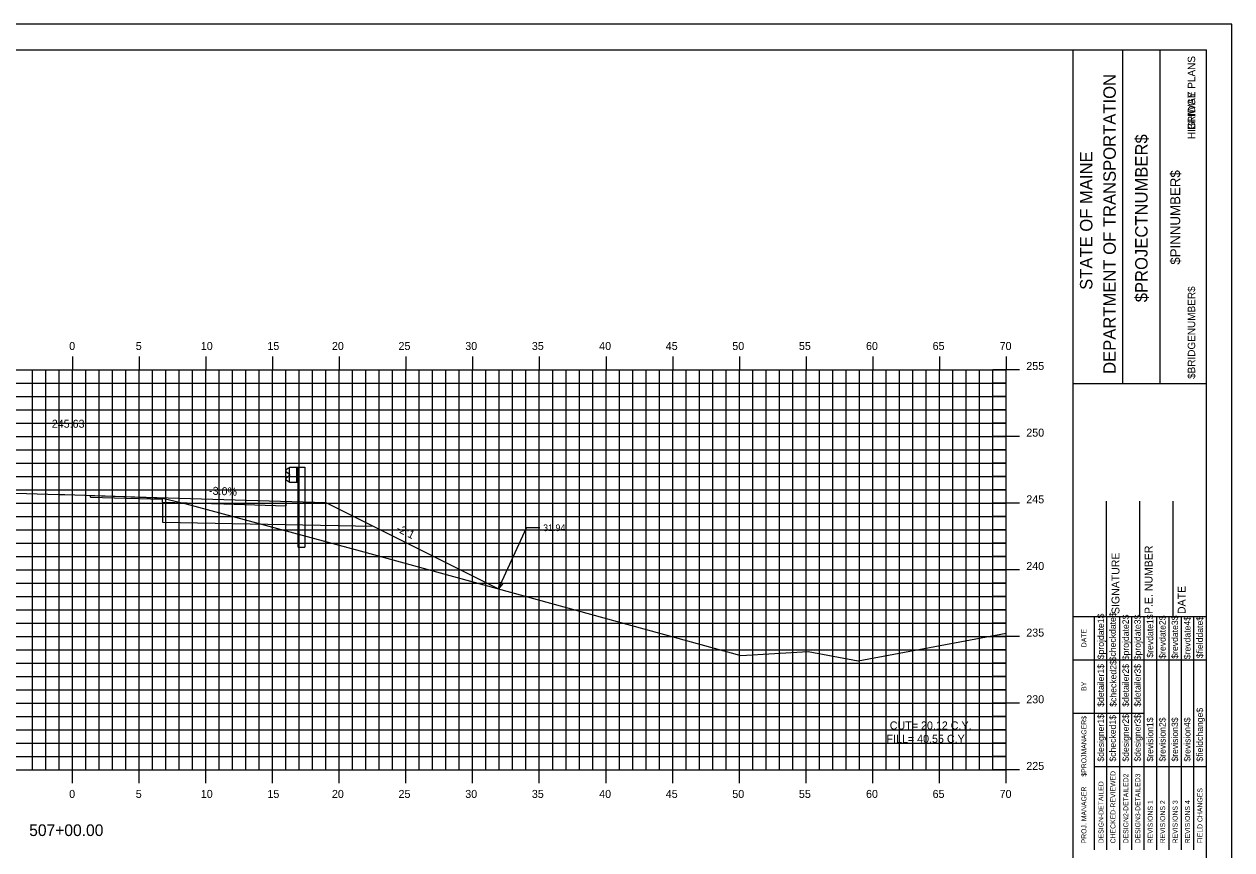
# Model space of a CAD drawing. Extents: x 1170543 to 1177585, y 609599 to 610623.
# Drawn here: x 1171583.6 to 1171674.1, y 609646.9 to 609708.8 of the extents above; entities that cross this region are included whole.
import ezdxf

# ---------------------------------------------------------------- set-up
doc = ezdxf.new("R2010")
doc.units = 0
for name, color, linetype in [('ANNOTATION', 7, 'Continuous'), ('BORDER', 7, 'Continuous'), ('BRIDGE_TITLE', 7, 'Continuous'), ('D_Guardrail_Beam_Rt', 7, 'Continuous'), ('D_Roadway_Centerline', 7, 'Continuous'), ('D_Roadway_Centerline_Text', 7, 'Continuous'), ('H_V ANNOTATION', 7, 'Continuous'), ('HIGHWAY_TITLE', 7, 'Continuous'), ('MAJOR', 7, 'Continuous'), ('MINOR', 7, 'Continuous'), ('PLOT BOUNDARY', 7, 'Continuous'), ('S_Roadway_Centerline', 7, 'Continuous'), ('SHADING', 7, 'Continuous')]:
    doc.layers.add(name, color=color, linetype=linetype)

msp = doc.modelspace()

# ---------------------------------------------------------------- linework, layer by layer
at = {"layer": 'ANNOTATION'}
for p, q in [((1171588.564, 609673.337), (1171588.564, 609673.462)), ((1171593.964, 609672.966), (1171593.964, 609673.3)), ((1171593.964, 609672.966), (1171593.964, 609671.466)), ((1171603.205, 609673.022), (1171603.205, 609672.689)), ((1171619.15, 609666.458), (1171621.24, 609671.034)), ((1171622.24, 609671.034), (1171621.24, 609671.034))]:
    msp.add_line(p, q, dxfattribs=at)
for points in [[(1171588.564, 609673.462), (1171598.564, 609673.162), (1171606.2, 609672.933)], [(1171588.564, 609673.337), (1171593.964, 609673.175)], [(1171593.964, 609672.966), (1171598.564, 609672.828), (1171603.205, 609672.689)], [(1171606.2, 609672.933), (1171608.2, 609671.933), (1171619.15, 609666.458)]]:
    msp.add_lwpolyline(points, dxfattribs=at)
msp.add_lwpolyline([(1171619.471, 609666.861), (1171619.15, 609666.458), (1171619.244, 609666.964)], close=True, dxfattribs=at)
at = {"layer": 'BORDER'}
for p, q in [((1171672.209, 609706.872), (1171512.209, 609706.872)), ((1171662.209, 609601.875), (1171662.209, 609706.875)), ((1171665.937, 609681.869), (1171665.937, 609706.869)), ((1171668.732, 609681.869), (1171668.732, 609706.869)), ((1171672.209, 609601.875), (1171672.209, 609706.875)), ((1171662.209, 609681.866), (1171672.209, 609681.866)), ((1171664.709, 609664.375), (1171664.709, 609673.023)), ((1171667.209, 609664.375), (1171667.209, 609673.023)), ((1171669.709, 609664.375), (1171669.709, 609673.023)), ((1171662.209, 609664.375), (1171672.209, 609664.375))]:
    msp.add_line(p, q, dxfattribs=at)
for points in [[(1171663.823, 609661.125), (1171663.823, 609664.375)], [(1171664.756, 609646.878), (1171664.756, 609664.375)], [(1171665.688, 609664.375), (1171665.688, 609646.878)], [(1171666.619, 609646.878), (1171666.619, 609664.375)], [(1171667.551, 609646.878), (1171667.551, 609664.375)], [(1171668.483, 609646.878), (1171668.483, 609664.375)], [(1171669.414, 609646.878), (1171669.414, 609664.375)], [(1171670.346, 609646.878), (1171670.346, 609664.375)], [(1171671.278, 609646.878), (1171671.278, 609664.375)], [(1171663.824, 609646.878), (1171663.824, 609663.669)], [(1171662.209, 609661.125), (1171672.209, 609661.125)], [(1171662.209, 609657.125), (1171663.824, 609657.125)], [(1171663.823, 609657.125), (1171667.55, 609657.125)], [(1171663.823, 609653.125), (1171672.209, 609653.125)]]:
    msp.add_lwpolyline(points, dxfattribs=at)
at = {"layer": 'D_Guardrail_Beam_Rt'}
for p, q in [((1171603.386, 609675.483), (1171603.243, 609675.383)), ((1171603.243, 609675.239), (1171603.438, 609675.103)), ((1171603.438, 609674.904), (1171603.243, 609674.768)), ((1171603.476, 609675.504), (1171603.402, 609675.489)), ((1171603.472, 609675.039), (1171603.472, 609674.969)), ((1171603.476, 609675.587), (1171604.163, 609675.587)), ((1171603.476, 609674.42), (1171603.476, 609675.587)), ((1171603.997, 609675.587), (1171603.997, 609674.42)), ((1171604.101, 609675.587), (1171604.101, 609674.42)), ((1171604.163, 609675.587), (1171604.634, 609675.587)), ((1171604.163, 609675.587), (1171604.163, 609674.42)), ((1171604.634, 609675.587), (1171604.634, 609669.587)), ((1171603.243, 609674.625), (1171603.386, 609674.525)), ((1171603.402, 609674.518), (1171603.476, 609674.504)), ((1171604.163, 609674.42), (1171603.476, 609674.42)), ((1171604.143, 609669.587), (1171604.143, 609674.42)), ((1171604.143, 609669.587), (1171604.634, 609669.587))]:
    msp.add_line(p, q, dxfattribs=at)
for centre, major_axis, start_param, end_param in [((1171603.293, 609675.311), (-0.0877, 0), 5.323254, 7.243116), ((1171603.41, 609675.449), (-0.0417, 0), 4.907132, 5.323254), ((1171603.393, 609675.039), (0.0789, 0), 0, 0.959931), ((1171603.393, 609674.969), (0.0789, 0), 5.323254, 6.283185), ((1171603.293, 609674.697), (-0.0877, 0), 5.323254, 7.243116), ((1171603.41, 609674.559), (-0.0417, 0), 0.959931, 1.376053)]:
    msp.add_ellipse(centre, major_axis=major_axis, ratio=0.995501, start_param=start_param, end_param=end_param, dxfattribs=at)
at = {"layer": 'MAJOR'}
for p, q in [((1171587.208, 609683.874), (1171587.208, 609682.872)), ((1171592.208, 609683.874), (1171592.208, 609682.872)), ((1171597.208, 609683.874), (1171597.208, 609682.872)), ((1171602.208, 609683.874), (1171602.208, 609682.872)), ((1171607.208, 609683.874), (1171607.208, 609682.872)), ((1171612.208, 609683.874), (1171612.208, 609682.872)), ((1171617.208, 609683.874), (1171617.208, 609682.872)), ((1171622.208, 609683.874), (1171622.208, 609682.872)), ((1171627.208, 609683.874), (1171627.208, 609682.872)), ((1171632.208, 609683.874), (1171632.208, 609682.872)), ((1171637.208, 609683.874), (1171637.208, 609682.872)), ((1171642.208, 609683.874), (1171642.208, 609682.872)), ((1171647.208, 609683.874), (1171647.208, 609682.872)), ((1171652.208, 609683.874), (1171652.208, 609682.872)), ((1171657.208, 609683.874), (1171657.208, 609682.872)), ((1171517.208, 609682.872), (1171657.208, 609682.872)), ((1171517.208, 609682.872), (1171657.208, 609682.872)), ((1171587.208, 609652.872), (1171587.208, 609682.872)), ((1171592.208, 609652.872), (1171592.208, 609682.872)), ((1171597.208, 609652.872), (1171597.208, 609682.872)), ((1171602.208, 609652.872), (1171602.208, 609682.872)), ((1171607.208, 609652.872), (1171607.208, 609682.872)), ((1171612.208, 609652.872), (1171612.208, 609682.872)), ((1171617.208, 609652.872), (1171617.208, 609682.872)), ((1171622.208, 609652.872), (1171622.208, 609682.872)), ((1171627.208, 609652.872), (1171627.208, 609682.872)), ((1171632.208, 609652.872), (1171632.208, 609682.872)), ((1171637.208, 609652.872), (1171637.208, 609682.872)), ((1171642.208, 609652.872), (1171642.208, 609682.872)), ((1171647.208, 609652.872), (1171647.208, 609682.872)), ((1171652.208, 609652.872), (1171652.208, 609682.872)), ((1171658.21, 609682.872), (1171656.206, 609682.872)), ((1171657.208, 609652.872), (1171657.208, 609682.872)), ((1171657.208, 609652.872), (1171657.208, 609682.872)), ((1171517.208, 609677.872), (1171657.208, 609677.872)), ((1171658.21, 609677.872), (1171656.206, 609677.872)), ((1171517.208, 609672.872), (1171657.208, 609672.872)), ((1171658.21, 609672.872), (1171656.206, 609672.872)), ((1171517.208, 609667.872), (1171657.208, 609667.872)), ((1171658.21, 609667.872), (1171656.206, 609667.872)), ((1171517.208, 609662.872), (1171657.208, 609662.872)), ((1171658.21, 609662.872), (1171656.206, 609662.872)), ((1171517.208, 609657.872), (1171657.208, 609657.872)), ((1171658.21, 609657.872), (1171656.206, 609657.872)), ((1171517.208, 609652.872), (1171657.208, 609652.872)), ((1171517.208, 609652.872), (1171657.208, 609652.872)), ((1171587.208, 609651.87), (1171587.208, 609652.872)), ((1171592.208, 609651.87), (1171592.208, 609652.872)), ((1171597.208, 609651.87), (1171597.208, 609652.872)), ((1171602.208, 609651.87), (1171602.208, 609652.872)), ((1171607.208, 609651.87), (1171607.208, 609652.872)), ((1171612.208, 609651.87), (1171612.208, 609652.872)), ((1171617.208, 609651.87), (1171617.208, 609652.872)), ((1171622.208, 609651.87), (1171622.208, 609652.872)), ((1171627.208, 609651.87), (1171627.208, 609652.872)), ((1171632.208, 609651.87), (1171632.208, 609652.872)), ((1171637.208, 609651.87), (1171637.208, 609652.872)), ((1171642.208, 609651.87), (1171642.208, 609652.872)), ((1171647.208, 609651.87), (1171647.208, 609652.872)), ((1171652.208, 609651.87), (1171652.208, 609652.872)), ((1171658.21, 609652.872), (1171656.206, 609652.872)), ((1171657.208, 609651.87), (1171657.208, 609652.872))]:
    msp.add_line(p, q, dxfattribs=at)
at = {"layer": 'MINOR'}
for p, q in [((1171584.208, 609652.872), (1171584.208, 609682.872)), ((1171585.208, 609652.872), (1171585.208, 609682.872)), ((1171586.208, 609652.872), (1171586.208, 609682.872)), ((1171588.208, 609652.872), (1171588.208, 609682.872)), ((1171589.208, 609652.872), (1171589.208, 609682.872)), ((1171590.208, 609652.872), (1171590.208, 609682.872)), ((1171591.208, 609652.872), (1171591.208, 609682.872)), ((1171593.208, 609652.872), (1171593.208, 609682.872)), ((1171594.208, 609652.872), (1171594.208, 609682.872)), ((1171595.208, 609652.872), (1171595.208, 609682.872)), ((1171596.208, 609652.872), (1171596.208, 609682.872)), ((1171598.208, 609652.872), (1171598.208, 609682.872)), ((1171599.208, 609652.872), (1171599.208, 609682.872)), ((1171600.208, 609652.872), (1171600.208, 609682.872)), ((1171601.208, 609652.872), (1171601.208, 609682.872)), ((1171603.208, 609652.872), (1171603.208, 609682.872)), ((1171604.208, 609652.872), (1171604.208, 609682.872)), ((1171605.208, 609652.872), (1171605.208, 609682.872)), ((1171606.208, 609652.872), (1171606.208, 609682.872)), ((1171608.208, 609652.872), (1171608.208, 609682.872)), ((1171609.208, 609652.872), (1171609.208, 609682.872)), ((1171610.208, 609652.872), (1171610.208, 609682.872)), ((1171611.208, 609652.872), (1171611.208, 609682.872)), ((1171613.208, 609652.872), (1171613.208, 609682.872)), ((1171614.208, 609652.872), (1171614.208, 609682.872)), ((1171615.208, 609652.872), (1171615.208, 609682.872)), ((1171616.208, 609652.872), (1171616.208, 609682.872)), ((1171618.208, 609652.872), (1171618.208, 609682.872)), ((1171619.208, 609652.872), (1171619.208, 609682.872)), ((1171620.208, 609652.872), (1171620.208, 609682.872)), ((1171621.208, 609652.872), (1171621.208, 609682.872)), ((1171623.208, 609652.872), (1171623.208, 609682.872)), ((1171624.208, 609652.872), (1171624.208, 609682.872)), ((1171625.208, 609652.872), (1171625.208, 609682.872)), ((1171626.208, 609652.872), (1171626.208, 609682.872)), ((1171628.208, 609652.872), (1171628.208, 609682.872)), ((1171629.208, 609652.872), (1171629.208, 609682.872)), ((1171630.208, 609652.872), (1171630.208, 609682.872)), ((1171631.208, 609652.872), (1171631.208, 609682.872)), ((1171633.208, 609652.872), (1171633.208, 609682.872)), ((1171634.208, 609652.872), (1171634.208, 609682.872)), ((1171635.208, 609652.872), (1171635.208, 609682.872)), ((1171636.208, 609652.872), (1171636.208, 609682.872)), ((1171638.208, 609652.872), (1171638.208, 609682.872)), ((1171639.208, 609652.872), (1171639.208, 609682.872)), ((1171640.208, 609652.872), (1171640.208, 609682.872)), ((1171641.208, 609652.872), (1171641.208, 609682.872)), ((1171643.208, 609652.872), (1171643.208, 609682.872)), ((1171644.208, 609652.872), (1171644.208, 609682.872)), ((1171645.208, 609652.872), (1171645.208, 609682.872)), ((1171646.208, 609652.872), (1171646.208, 609682.872)), ((1171648.208, 609652.872), (1171648.208, 609682.872)), ((1171649.208, 609652.872), (1171649.208, 609682.872)), ((1171650.208, 609652.872), (1171650.208, 609682.872)), ((1171651.208, 609652.872), (1171651.208, 609682.872)), ((1171653.208, 609652.872), (1171653.208, 609682.872)), ((1171654.208, 609652.872), (1171654.208, 609682.872)), ((1171655.208, 609652.872), (1171655.208, 609682.872)), ((1171656.208, 609652.872), (1171656.208, 609682.872)), ((1171517.208, 609681.872), (1171657.208, 609681.872)), ((1171657.208, 609681.872), (1171656.206, 609681.872)), ((1171517.208, 609680.872), (1171657.208, 609680.872)), ((1171657.208, 609680.872), (1171656.206, 609680.872)), ((1171517.208, 609679.872), (1171657.208, 609679.872)), ((1171657.208, 609679.872), (1171656.206, 609679.872)), ((1171517.208, 609678.872), (1171657.208, 609678.872)), ((1171657.208, 609678.872), (1171656.206, 609678.872)), ((1171517.208, 609676.872), (1171657.208, 609676.872)), ((1171657.208, 609676.872), (1171656.206, 609676.872)), ((1171517.208, 609675.872), (1171657.208, 609675.872)), ((1171657.208, 609675.872), (1171656.206, 609675.872)), ((1171517.208, 609674.872), (1171657.208, 609674.872)), ((1171657.208, 609674.872), (1171656.206, 609674.872)), ((1171517.208, 609673.872), (1171657.208, 609673.872)), ((1171657.208, 609673.872), (1171656.206, 609673.872)), ((1171517.208, 609671.872), (1171657.208, 609671.872)), ((1171657.208, 609671.872), (1171656.206, 609671.872)), ((1171517.208, 609670.872), (1171657.208, 609670.872)), ((1171657.208, 609670.872), (1171656.206, 609670.872)), ((1171517.208, 609669.872), (1171657.208, 609669.872)), ((1171657.208, 609669.872), (1171656.206, 609669.872)), ((1171517.208, 609668.872), (1171657.208, 609668.872)), ((1171657.208, 609668.872), (1171656.206, 609668.872)), ((1171517.208, 609666.872), (1171657.208, 609666.872)), ((1171657.208, 609666.872), (1171656.206, 609666.872)), ((1171517.208, 609665.872), (1171657.208, 609665.872)), ((1171657.208, 609665.872), (1171656.206, 609665.872)), ((1171517.208, 609664.872), (1171657.208, 609664.872)), ((1171657.208, 609664.872), (1171656.206, 609664.872)), ((1171517.208, 609663.872), (1171657.208, 609663.872)), ((1171657.208, 609663.872), (1171656.206, 609663.872)), ((1171517.208, 609661.872), (1171657.208, 609661.872)), ((1171657.208, 609661.872), (1171656.206, 609661.872)), ((1171517.208, 609660.872), (1171657.208, 609660.872)), ((1171657.208, 609660.872), (1171656.206, 609660.872)), ((1171517.208, 609659.872), (1171657.208, 609659.872)), ((1171657.208, 609659.872), (1171656.206, 609659.872)), ((1171517.208, 609658.872), (1171657.208, 609658.872)), ((1171657.208, 609658.872), (1171656.206, 609658.872)), ((1171517.208, 609656.872), (1171657.208, 609656.872)), ((1171657.208, 609656.872), (1171656.206, 609656.872)), ((1171517.208, 609655.872), (1171657.208, 609655.872)), ((1171657.208, 609655.872), (1171656.206, 609655.872)), ((1171517.208, 609654.872), (1171657.208, 609654.872)), ((1171657.208, 609654.872), (1171656.206, 609654.872)), ((1171517.208, 609653.872), (1171657.208, 609653.872)), ((1171657.208, 609653.872), (1171656.206, 609653.872))]:
    msp.add_line(p, q, dxfattribs=at)
at = {"layer": 'PLOT BOUNDARY'}
msp.add_lwpolyline([(1171504.115, 609598.813), (1171674.115, 609598.813), (1171674.115, 609708.813), (1171504.115, 609708.813)], close=True, dxfattribs=at)
at = {"layer": 'S_Roadway_Centerline'}
msp.add_lwpolyline([(1171581.352, 609673.678), (1171586.162, 609673.542), (1171586.642, 609673.526), (1171591.169, 609673.375), (1171591.591, 609673.357), (1171593.964, 609673.255), (1171594.293, 609673.174), (1171595.732, 609672.829), (1171608.777, 609669.318), (1171637.3, 609661.452), (1171642.365, 609661.747), (1171646.109, 609661.061), (1171657.208, 609663.131)], dxfattribs=at)
at = {"layer": 'SHADING'}
msp.add_line((1171593.964, 609671.466), (1171609.765, 609671.15), dxfattribs=at)

# ---------------------------------------------------------------- texts
at = {"layer": 'ANNOTATION'}
for s, rotation, p in [('-3.0%', 357.80885, (1171597.441, 609673.523)), ('-2:1', 333.37406, (1171611.439, 609670.799))]:
    msp.add_text(s, height=0.6, rotation=rotation, dxfattribs=at).set_placement(p)
msp.add_text("31.94'", height=0.5, dxfattribs=at).set_placement((1171622.49, 609670.784))
at = {"layer": 'BORDER'}
for s, height, p in [('DEPARTMENT OF TRANSPORTATION', 0.93176, (1171665.415, 609682.578)), ('$PROJECTNUMBER$', 0.93176, (1171667.8, 609687.951)), ('STATE OF MAINE', 0.93176, (1171663.664, 609688.884)), ('$PINNUMBER$', 0.74527, (1171670.245, 609690.769)), ('P.E. NUMBER', 0.59055, (1171668.169, 609664.567)), ('SIGNATURE', 0.5906, (1171665.689, 609664.567)), ('DATE', 0.5906, (1171670.65, 609664.567)), ('$projdate1$', 0.48455, (1171664.531, 609661.176)), ('$checkdate$', 0.48455, (1171665.426, 609661.018)), ('$projdate2$', 0.48455, (1171666.395, 609661.097)), ('$projdate3$', 0.48455, (1171667.289, 609661.097)), ('$revdate1$', 0.4845, (1171668.221, 609661.294)), ('$revdate2$', 0.4845, (1171669.153, 609661.215)), ('$revdate3$', 0.4845, (1171670.084, 609661.215)), ('$revdate4$', 0.4845, (1171671.016, 609661.176)), ('$fielddate$', 0.48455, (1171671.948, 609661.254)), ('DATE', 0.3714, (1171663.213, 609662.081)), ('$detailer1$', 0.48455, (1171664.531, 609657.61)), ('$checked2$', 0.4845, (1171665.463, 609657.61)), ('$detailer2$', 0.48455, (1171666.395, 609657.61)), ('$detailer3$', 0.48455, (1171667.289, 609657.61)), ('BY', 0.3714, (1171663.213, 609658.81)), ('$PROJMANAGER$', 0.37275, (1171663.213, 609652.37)), ('$designer1$', 0.48455, (1171664.531, 609653.498)), ('$checked1$', 0.4845, (1171665.426, 609653.498)), ('$designer2$', 0.48455, (1171666.395, 609653.498)), ('$designer3$', 0.48455, (1171667.289, 609653.498)), ('$revision1$', 0.48455, (1171668.221, 609653.498)), ('$revision2$', 0.48455, (1171669.153, 609653.498)), ('$revision3$', 0.48455, (1171670.084, 609653.498)), ('$revision4$', 0.48455, (1171671.016, 609653.498)), ('$fieldchange$', 0.48455, (1171671.948, 609653.498)), ('CHECKED-REVIEWED', 0.37275, (1171665.39, 609647.363)), ('DESIGN2-DETAILED2', 0.37275, (1171666.358, 609647.363)), ('DESIGN3-DETAILED3', 0.37275, (1171667.253, 609647.363)), ('PROJ. MANAGER', 0.37275, (1171663.213, 609647.363)), ('DESIGN-DETAILED', 0.37275, (1171664.495, 609647.363)), ('FIELD CHANGES', 0.37275, (1171671.911, 609647.363)), ('REVISIONS 1', 0.37275, (1171668.185, 609647.363)), ('REVISIONS 2', 0.37275, (1171669.116, 609647.363)), ('REVISIONS 3', 0.37275, (1171670.048, 609647.363)), ('REVISIONS 4', 0.37275, (1171670.98, 609647.363))]:
    msp.add_text(s, height=height, rotation=90, dxfattribs=at).set_placement(p)
at = {"layer": 'BRIDGE_TITLE'}
for s, p in [('BRIDGE PLANS', (1171671.367, 609700.897)), ('$BRIDGENUMBER$', (1171671.367, 609682.203))]:
    msp.add_text(s, height=0.55901, rotation=90, dxfattribs=at).set_placement(p)
at = {"layer": 'D_Roadway_Centerline'}
for s, p in [('C', (1171587.203, 609673.507)), ('L', (1171587.208, 609673.5))]:
    msp.add_text(s, height=0.0146, dxfattribs=at).set_placement(p)
at = {"layer": 'D_Roadway_Centerline_Text'}
for s, p in [('245.63', (1171585.664, 609678.539)), ('CUT= 20.12 C.Y.', (1171648.476, 609655.908)), ('FILL= 40.55 C.Y.', (1171648.23, 609654.906))]:
    msp.add_text(s, height=0.6, dxfattribs=at).set_placement(p)
at = {"layer": 'H_V ANNOTATION'}
for s, height, p in [('0', 0.6, (1171586.967, 609684.372)), ('5', 0.6, (1171591.959, 609684.372)), ('10', 0.6, (1171596.834, 609684.372)), ('15', 0.6, (1171601.826, 609684.372)), ('20', 0.6, (1171606.662, 609684.372)), ('25', 0.6, (1171611.654, 609684.372)), ('30', 0.6, (1171616.657, 609684.372)), ('35', 0.6, (1171621.649, 609684.372)), ('40', 0.6, (1171626.694, 609684.372)), ('45', 0.6, (1171631.686, 609684.372)), ('50', 0.6, (1171636.673, 609684.372)), ('55', 0.6, (1171641.665, 609684.372)), ('60', 0.6, (1171646.694, 609684.372)), ('65', 0.6, (1171651.686, 609684.372)), ('70', 0.6, (1171656.71, 609684.372)), ('255', 0.6, (1171658.708, 609682.872)), ('250', 0.6, (1171658.708, 609677.872)), ('245', 0.6, (1171658.708, 609672.872)), ('240', 0.6, (1171658.708, 609667.872)), ('235', 0.6, (1171658.708, 609662.872)), ('230', 0.6, (1171658.708, 609657.872)), ('225', 0.6, (1171658.708, 609652.872)), ('0', 0.6, (1171586.967, 609650.772)), ('5', 0.6, (1171591.959, 609650.772)), ('10', 0.6, (1171596.834, 609650.772)), ('15', 0.6, (1171601.826, 609650.772)), ('20', 0.6, (1171606.662, 609650.772)), ('25', 0.6, (1171611.654, 609650.772)), ('30', 0.6, (1171616.657, 609650.772)), ('35', 0.6, (1171621.649, 609650.772)), ('40', 0.6, (1171626.694, 609650.772)), ('45', 0.6, (1171631.686, 609650.772)), ('50', 0.6, (1171636.673, 609650.772)), ('55', 0.6, (1171641.665, 609650.772)), ('60', 0.6, (1171646.694, 609650.772)), ('65', 0.6, (1171651.686, 609650.772)), ('70', 0.6, (1171656.71, 609650.772)), ('507+00.00', 0.875, (1171583.97, 609647.915))]:
    msp.add_text(s, height=height, dxfattribs=at).set_placement(p)
at = {"layer": 'HIGHWAY_TITLE'}
msp.add_text('HIGHWAY PLANS', height=0.55901, rotation=90, dxfattribs=at).set_placement((1171671.367, 609700.188))

doc.saveas('drawing.dxf')
